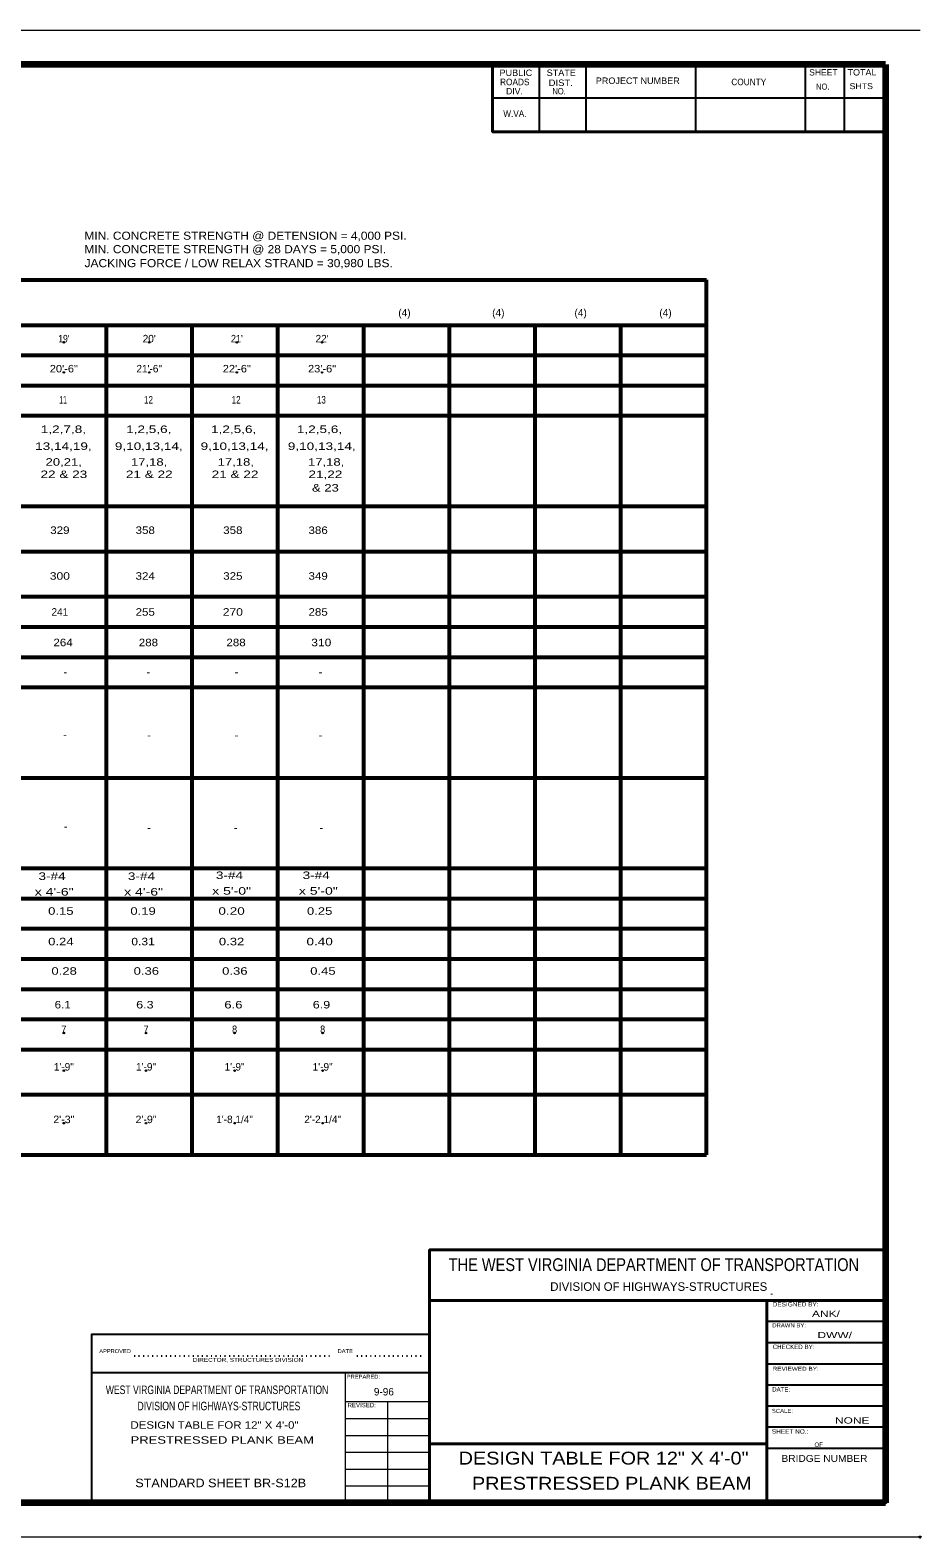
# Model space of a CAD drawing. Extents: x 758 to 1184, y 2441 to 2716.
# Drawn here: x 1021.3 to 1183.7, y 2440.9 to 2716.1 of the extents above; entities that cross this region are included whole.
import ezdxf
from ezdxf.enums import TextEntityAlignment as Align

# ---------------------------------------------------------------- set-up
doc = ezdxf.new("R2010")
doc.units = 0
doc.header["$LTSCALE"] = 0.55
doc.header["$PDMODE"] = 32
doc.header["$PDSIZE"] = 0.275
doc.linetypes.add('DOTTED', pattern=[1.5, 0.3, -1.2])
for name, color, linetype, lineweight in [('1', 7, 'Continuous', 25), ('20', 7, 'Continuous', 13), ('61', 7, 'Continuous', 13), ('7', 7, 'Continuous', 53)]:
    doc.layers.add(name, color=color, linetype=linetype, lineweight=lineweight)
for name, color, linetype in [('14', 7, 'Continuous'), ('2', 7, 'Continuous'), ('21', 7, 'Continuous')]:
    doc.layers.add(name, color=color, linetype=linetype)

msp = doc.modelspace()

# ---------------------------------------------------------------- linework, layer by layer
at = {"layer": '1'}
for p, q in [((1114.1408, 2709.8172), (1114.1408, 2697.5172)), ((1122.6283, 2709.8172), (1122.6283, 2697.5172)), ((1142.6408, 2709.8172), (1142.6408, 2697.5172)), ((1162.6283, 2709.8172), (1162.6283, 2697.5172)), ((1169.7283, 2709.8172), (1169.7283, 2697.5172)), ((1105.6408, 2703.6797), (1177.2783, 2703.6797)), ((1156.5408, 2485.3422), (1156.5408, 2485.4172)), ((1155.6533, 2480.4297), (1177.2783, 2480.4297)), ((1155.6533, 2476.5422), (1177.2783, 2476.5422)), ((1032.5408, 2471.1172), (1094.1408, 2471.1172)), ((1155.6533, 2472.6672), (1177.2783, 2472.6672)), ((1155.6533, 2468.8422), (1177.2783, 2468.8422)), ((1155.6533, 2464.9797), (1177.2783, 2464.9797)), ((1155.6533, 2461.1672), (1177.2783, 2461.1672)), ((1155.6533, 2457.2672), (1177.2783, 2457.2672))]:
    msp.add_line(p, q, dxfattribs=at)
at = {"layer": '1', "lineweight": 40}
for p, q in [((1094.1408, 2484.2422), (1177.2783, 2484.2422)), ((1155.6533, 2484.2422), (1155.6533, 2447.3172)), ((1094.1408, 2458.0797), (1155.6533, 2458.0797))]:
    msp.add_line(p, q, dxfattribs=at)
at = {"layer": '1', "lineweight": 13}
for p, q in [((1078.7533, 2471.1172), (1078.7533, 2447.3172)), ((1078.7533, 2465.7922), (1094.1408, 2465.7922)), ((1086.4408, 2465.8547), (1086.4408, 2447.3172)), ((1078.7533, 2462.7047), (1094.1408, 2462.7047)), ((1078.7533, 2459.6172), (1094.1408, 2459.6172)), ((1078.7533, 2456.5422), (1094.1408, 2456.5422)), ((1078.7533, 2453.4797), (1094.1408, 2453.4797)), ((1078.7533, 2450.3922), (1094.1408, 2450.3922))]:
    msp.add_line(p, q, dxfattribs=at)
at = {"layer": '1', "lineweight": 40}
for points in [[(1105.6408, 2709.8172), (1105.6408, 2697.5172), (1177.2783, 2697.5172)], [(1094.1408, 2447.3172), (1094.1408, 2493.4672), (1177.2783, 2493.4672)]]:
    msp.add_lwpolyline(points, dxfattribs=at)
at = {"layer": '1'}
msp.add_lwpolyline([(1032.5408, 2447.3172), (1032.5408, 2478.0797), (1094.1408, 2478.0797)], dxfattribs=at)
for p in [(1177.2783, 2447.3172), (1183.5658, 2441.0547)]:
    msp.add_point(p, dxfattribs=at)
at = {"layer": '20'}
for p in [(1027.4567, 2659.0739), (1043.0199, 2659.0739), (1058.9948, 2659.0739), (1074.542, 2659.0739), (1027.4567, 2653.5941), (1043.0199, 2653.5941), (1058.9948, 2653.5941), (1074.542, 2653.5941), (1027.4567, 2533.0363), (1042.4435, 2533.0363), (1058.5831, 2533.0363), (1074.6403, 2533.0363), (1027.4567, 2526.1863), (1042.4435, 2526.1863), (1058.5831, 2526.1863), (1074.6403, 2526.1863), (1027.4567, 2516.5967), (1042.4435, 2516.5967), (1058.5831, 2516.5967), (1074.6403, 2516.5967)]:
    msp.add_point(p, dxfattribs=at)
at = {"layer": '61'}
for p, q in [((758.5283, 2716.0547), (1183.5658, 2716.0547)), ((1183.5658, 2441.0547), (758.5283, 2441.0547))]:
    msp.add_line(p, q, dxfattribs=at)
at = {"layer": '61', "lineweight": 158}
for p, q in [((1177.2783, 2709.8172), (788.5283, 2709.8172)), ((1177.2783, 2709.8172), (1177.2783, 2447.3172)), ((1177.2783, 2447.3172), (788.5283, 2447.3172))]:
    msp.add_line(p, q, dxfattribs=at)
at = {"layer": '7'}
for p, q in [((816.6381, 2670.4996), (1144.6256, 2670.4996)), ((1144.6256, 2510.7871), (1144.6256, 2670.4996)), ((816.6381, 2662.2371), (1144.6256, 2662.2371)), ((1035.2506, 2510.7871), (1035.2506, 2662.2371)), ((1050.8756, 2510.7871), (1050.8756, 2662.2371)), ((1066.5006, 2510.7871), (1066.5006, 2662.2371)), ((1082.1256, 2510.7871), (1082.1256, 2662.2371)), ((1097.7506, 2510.7871), (1097.7506, 2662.2371)), ((1113.3756, 2510.7871), (1113.3756, 2662.2371)), ((1129.0006, 2510.7871), (1129.0006, 2662.2371)), ((1144.6256, 2510.7871), (1144.6256, 2662.2371)), ((816.6381, 2656.7246), (1144.6256, 2656.7246)), ((816.6381, 2651.2246), (1144.6256, 2651.2246)), ((816.6381, 2645.7121), (1144.6256, 2645.7121)), ((816.6381, 2629.1871), (1144.6256, 2629.1871)), ((816.6381, 2620.9371), (1144.6256, 2620.9371)), ((816.6381, 2612.6746), (1144.6256, 2612.6746)), ((816.6381, 2607.1621), (1144.6256, 2607.1621)), ((816.6381, 2601.6496), (1144.6256, 2601.6496)), ((816.6381, 2596.1496), (1144.6256, 2596.1496)), ((816.6381, 2579.6246), (1144.6256, 2579.6246)), ((816.6381, 2563.0996), (1144.6256, 2563.0996)), ((816.6381, 2557.5996), (1144.6256, 2557.5996)), ((831.7881, 2552.0871), (1144.6256, 2552.0871)), ((831.7881, 2546.5871), (1144.6256, 2546.5871)), ((816.6381, 2541.0746), (1144.6256, 2541.0746)), ((816.6381, 2535.5621), (1144.6256, 2535.5621)), ((849.6756, 2530.0621), (1144.6256, 2530.0621)), ((849.6756, 2521.7996), (1144.6256, 2521.7996)), ((849.6756, 2510.7871), (1144.6256, 2510.7871))]:
    msp.add_line(p, q, dxfattribs=at)
at = {"layer": '7', "linetype": 'DOTTED', "lineweight": 25}
for p, q in [((1040.2658, 2474.1547), (1076.3783, 2474.1547)), ((1080.8658, 2474.1547), (1093.0908, 2474.1547))]:
    msp.add_line(p, q, dxfattribs=at)

# ---------------------------------------------------------------- texts
at = {"layer": '1'}
for s, height, width, p in [('PUBLIC', 1.175, 1.05, (1109.8721, 2707.6922)), ('STATE', 1.175, 1.05, (1118.1533, 2707.6922)), ('PROJECT NUMBER', 1.175, 1.05, (1132.0971, 2706.2422)), ('TOTAL', 1.162, 1.05, (1172.9783, 2707.7797)), ('ROADS', 1.187, 0.95, (1109.6721, 2706.0047)), ('DIST.', 1.175, 1.1, (1118.0533, 2705.8672)), ('NO.', 1.175, 0.85, (1117.7471, 2704.3297)), ('COUNTY', 1.187, 0.95, (1152.3346, 2706.0047)), ('NO.', 1.1, 0.95, (1165.8221, 2705.2047)), ('SHTS', 1.087, 1.1, (1172.8408, 2705.2922)), ('W.VA.', 1.175, 0.95, (1109.6971, 2700.2297)), ('THE WEST VIRGINIA DEPARTMENT OF TRANSPORTATION', 2.337, 0.85, (1135.0346, 2489.6047)), ('BRIDGE NUMBER', 1.262, 1.1, (1166.1283, 2454.7797))]:
    msp.add_text(s, height=height, dxfattribs=dict(at, width=width)).set_placement(p, align=Align.CENTER)
for s, height, p in [('SHEET', 1.162, (1165.9346, 2707.7797)), ('DIV.', 1.175, (1109.6096, 2704.3297)), ('DIVISION OF HIGHWAYS-STRUCTURES ', 1.562, (1136.2096, 2485.9922))]:
    msp.add_text(s, height=height, dxfattribs=at).set_placement(p, align=Align.CENTER)
for s, height, width, p in [('DESIGNED BY:', 0.8001, 1.1, (1156.6908, 2483.1422)), ('DRAWN BY:', 0.7375, 1.1, (1156.6158, 2479.3297)), ('APPROVED', 0.7375, 1.05, (1033.9158, 2474.6297)), ('DIRECTOR, STRUCTURES DIVISION', 0.7249, 1.2, (1050.9908, 2473.0297)), ('DATE', 0.7375, 1.05, (1077.3824, 2474.6297)), ('REVIEWED BY:', 0.7249, 1.2, (1156.6908, 2471.4172)), ('PREPARED:', 0.7124, 1.1, (1079.0408, 2469.9672)), ('SCALE:', 0.7375, 1.1, (1156.5408, 2463.7172)), ('SHEET NO.:', 0.8001, 1.1, (1156.5408, 2459.9297)), ('OF', 0.8126, 0.85, (1164.3158, 2457.5047))]:
    msp.add_text(s, height=height, dxfattribs=dict(at, width=width)).set_placement(p)
for s, height, p in [('CHECKED BY:', 0.8126, (1156.6908, 2475.3672)), ('DATE:', 0.8001, (1156.6158, 2467.6172)), ('REVISED:', 0.8001, (1079.1908, 2464.7422))]:
    msp.add_text(s, height=height, dxfattribs=at).set_placement(p)
at = {"layer": '14'}
for s, height, width, p in [('ANK/    ', 1.125, 1.45, (1167.6108, 2481.2422)), ('  DWW/  ', 1.125, 1.45, (1168.008, 2477.3672)), ('  NONE  ', 1.125, 1.45, (1171.1923, 2461.7797)), ('     DESIGN TABLE FOR 12" X 4\'-0"    ', 1.362, 1.15, (1054.6306, 2460.8297)), ('     PRESTRESSED PLANK BEAM    ', 1.362, 1.3, (1056.0141, 2458.0922)), ('   DESIGN TABLE FOR 12" X 4\'-0" ', 2.35, 1.15, (1124.872, 2454.2922)), ('  STANDARD SHEET BR-S12B  ', 1.562, 1.1, (1056.0597, 2450.1547)), ('   PRESTRESSED PLANK BEAM  ', 2.35, 1.15, (1126.8738, 2449.7047))]:
    msp.add_text(s, height=height, dxfattribs=dict(at, width=width)).set_placement(p, align=Align.CENTER)
msp.add_text('9-96  ', height=1.362, dxfattribs=at).set_placement((1086.3132, 2466.9047), align=Align.CENTER)
at = {"layer": '2', "width": 0.75}
for s, p in [('WEST VIRGINIA DEPARTMENT OF TRANSPORTATION', (1055.3908, 2467.1547)), ('DIVISION OF HIGHWAYS-STRUCTURES', (1055.7283, 2464.1922))]:
    msp.add_text(s, height=1.562, dxfattribs=at).set_placement(p, align=Align.CENTER)
at = {"layer": '20'}
for s, width, p in [("19'", 0.85, (1027.4569, 2659.0739)), ("21'", 0.9, (1058.995, 2659.0739)), ('20\'-6"', 1.1, (1027.4569, 2653.5941)), ('22\'-6"', 1.1, (1058.995, 2653.5941)), ('23\'-6"', 1.1, (1074.5421, 2653.5941)), ('11', 0.55, (1027.3262, 2647.9171)), ('12', 0.8, (1042.8894, 2647.9171)), ('12', 0.8, (1058.8643, 2647.9171)), ('13', 0.8, (1074.4115, 2647.9171)), ('1,2,7,8,', 1.35, (1027.3774, 2642.5385)), ('1,2,5,6,', 1.35, (1042.9406, 2642.5385)), ('1,2,5,6,', 1.35, (1058.4214, 2642.5385)), ('1,2,5,6,', 1.35, (1074.0669, 2642.5385)), ('13,14,19,', 1.35, (1027.3774, 2639.4478)), ('9,10,13,14,', 1.35, (1042.9406, 2639.4478)), ('9,10,13,14,', 1.35, (1058.5861, 2639.4478)), ('9,10,13,14,', 1.35, (1074.4787, 2639.4478)), ('20,21,', 1.3, (1027.4369, 2636.5709)), ('17,18,', 1.3, (1043, 2636.5709)), ('17,18,', 1.3, (1058.8103, 2636.5709)), ('17,18,', 1.3, (1075.2793, 2636.5709)), ('22 & 23', 1.35, (1027.4643, 2634.3193)), ('21 & 22', 1.35, (1043.0275, 2634.3193)), ('21 & 22', 1.35, (1058.673, 2634.3193)), ('21,22', 1.35, (1075.142, 2634.3193)), ('& 23', 1.3, (1075.142, 2631.8471)), ('329', 1.15, (1026.7328, 2624.1177)), ('358', 1.15, (1042.296, 2624.1177)), ('358', 1.15, (1058.2709, 2624.1177)), ('386', 1.15, (1073.818, 2624.1177)), ('300', 1.2, (1026.7328, 2615.7627)), ('324', 1.15, (1042.296, 2615.7627)), ('325', 1.15, (1058.2709, 2615.7627)), ('349', 1.15, (1073.8181, 2615.7627)), ('255', 1.15, (1042.2961, 2609.1983)), ('270', 1.2, (1058.271, 2609.1983)), ('285', 1.15, (1073.8182, 2609.1983)), ('264', 1.15, (1027.3137, 2603.6283)), ('288', 1.15, (1042.8768, 2603.6283)), ('288', 1.15, (1058.8518, 2603.6283)), ('310', 1.2, (1074.3989, 2603.6283)), ('-', 1.1, (1027.7268, 2598.2574)), ('-', 1.1, (1042.8782, 2598.2574)), ('-', 1.1, (1058.9355, 2598.2574)), ('-', 1.1, (1074.2516, 2598.2574)), ('-', 1.1, (1027.645, 2586.7833)), ('-', 1.1, (1042.9606, 2586.7203)), ('-', 1.1, (1058.9355, 2586.7203)), ('-', 1.1, (1074.2516, 2586.7203)), ('-', 1.1, (1027.8075, 2570.0737)), ('-', 1.1, (1042.9606, 2569.8267)), ('-', 1.1, (1058.7707, 2569.8267)), ('-', 1.1, (1074.4163, 2569.8267)), ('0.15', 1.3, (1026.9127, 2554.6202)), ('0.19', 1.3, (1041.8995, 2554.6202)), ('0.20', 1.35, (1058.039, 2554.6202)), ('0.25', 1.3, (1074.0963, 2554.6202)), ('0.24', 1.3, (1026.9127, 2549.0504)), ('0.31', 1.2, (1041.8995, 2549.0504)), ('0.32', 1.3, (1058.0391, 2549.0504)), ('0.40', 1.35, (1074.0963, 2549.0504)), ('0.28', 1.3, (1027.5091, 2543.6793)), ('0.36', 1.3, (1042.4958, 2543.6793)), ('0.36', 1.3, (1058.6354, 2543.6793)), ('0.45', 1.3, (1074.6927, 2543.6793)), ('6.1', 1.15, (1027.2462, 2537.5252)), ('6.3', 1.25, (1042.233, 2537.5252)), ('6.6', 1.3, (1058.3725, 2537.5252)), ('6.9', 1.25, (1074.4298, 2537.5252)), ('7', 0.9, (1027.4625, 2533.0363)), ('7', 0.9, (1042.4492, 2533.0363)), ('8', 0.9, (1058.5888, 2533.0363)), ('8', 0.9, (1074.646, 2533.0363)), ('2\'-3"', 1.05, (1027.4566, 2516.5967)), ('2\'-9"', 1.05, (1042.4434, 2516.5967))]:
    msp.add_text(s, height=1.37, dxfattribs=dict(at, width=width)).set_placement(p, align=Align.CENTER)
for s, p in [("20'", (1043.02, 2659.0739)), ("22'", (1074.5421, 2659.0739)), ('21\'-6"', (1043.02, 2653.5941)), ('241', (1026.7329, 2609.1983)), ('1\'-9"', (1027.4567, 2526.1863)), ('1\'-9"', (1042.4435, 2526.1863)), ('1\'-9"', (1058.583, 2526.1863)), ('1\'-9"', (1074.6403, 2526.1863)), ('1\'-8 1/4"', (1058.583, 2516.5967)), ('2\'-2 1/4"', (1074.6402, 2516.5967))]:
    msp.add_text(s, height=1.37, dxfattribs=at).set_placement(p, align=Align.CENTER)
for s, width, p in [(' 3-#4', 1.35, (1022.1422, 2560.9783)), (' 3-#4', 1.35, (1038.4465, 2560.9783)), (' 3-#4', 1.35, (1054.4923, 2561.1473)), (' 3-#4', 1.35, (1070.3025, 2561.1473)), ('x 4\'-6"', 1.4, (1022.1422, 2558.1242)), ('x 4\'-6"', 1.4, (1038.4465, 2558.1242)), ('x 5\'-0"', 1.4, (1054.4923, 2558.2932)), ('x 5\'-0"', 1.4, (1070.3025, 2558.2932))]:
    msp.add_text(s, height=1.37, dxfattribs=dict(at, width=width)).set_placement(p)
at = {"layer": '21', "width": 1.1}
for s, p in [('MIN. CONCRETE STRENGTH @ DETENSION = 4,000 PSI.', (1031.1935, 2677.8057)), ('MIN. CONCRETE STRENGTH @ 28 DAYS = 5,000 PSI.', (1031.1935, 2675.3516))]:
    msp.add_text(s, height=1.48, dxfattribs=at).set_placement(p)
at = {"layer": '21'}
for p in [(1089.5602, 2663.8076), (1106.6746, 2663.8076), (1121.6789, 2663.8076), (1137.1522, 2663.8076)]:
    msp.add_text('(4)', height=1.37, dxfattribs=at).set_placement(p, align=Align.CENTER)
at = {"layer": '7', "width": 1.1}
msp.add_text('JACKING FORCE / LOW RELAX STRAND = 30,980 LBS.', height=1.48, dxfattribs=at).set_placement((1031.2352, 2672.7992))

doc.saveas('drawing.dxf')
